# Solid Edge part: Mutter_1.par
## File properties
Sűrűség: 0,000 kg/m^3
Pontosság: 0,990
Author: psaghy
Last saved by: ahadarics
Revision: 77
Username: psaghy
Dokumentum tartalom típus: 0
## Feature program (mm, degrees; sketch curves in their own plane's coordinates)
base feature "unnamed BaseFeature 1"
thread "unnamed Thread 1"
chamfer "Letörés_3"  SetBackValue2 = 60 deg
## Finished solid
Body 1: solid body, 23 faces, 46 edges, 24 vertices.
  Faces by surface: cone 14, plane 8, cylinder 1
  Edges by curve: spline 24, circle 16, line 6
Bounding box of the edges (mm): 7.000 x 21.939 x 19.000, from (0, -10.9697, -9.5) to (7, 10.9697, 9.5).
Cylindrical faces by radius (mm): R5.3235 x1
Conical faces (half-angle, radius in mm at the cone's reference point): 60 deg R5.3235 x1, 60 deg R6.0163 x1, 60 deg R10.2348 x12
Planar faces by outward normal: +x 1, +z 1, -x 1, -z 1, oblique 4
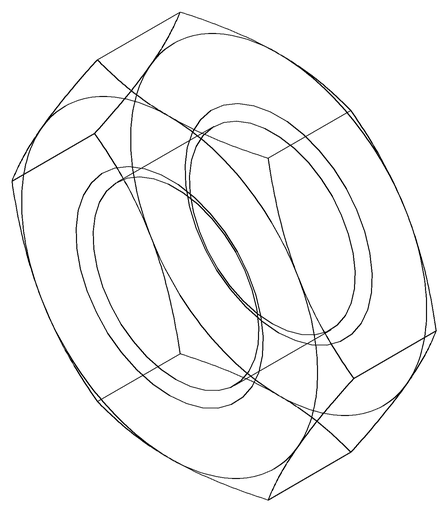
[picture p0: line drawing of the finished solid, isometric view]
